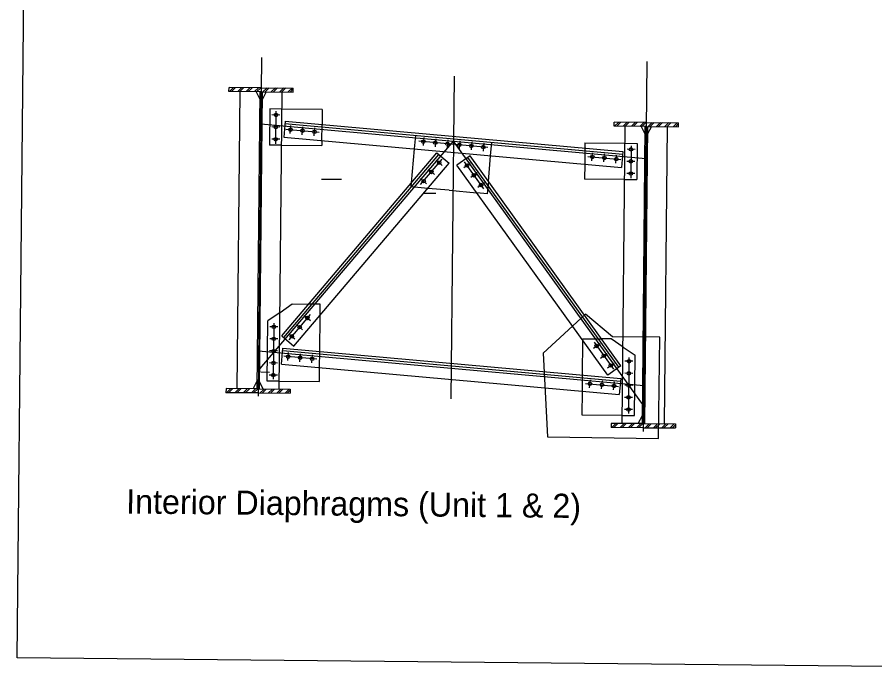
# Model space of a CAD drawing. Extents: x 632066 to 633140, y 373235 to 381884.
# Drawn here: x 632199.99 to 632217.79, y 378376.15 to 378389.8 of the extents above; entities that cross this region are included whole.
import ezdxf

# ---------------------------------------------------------------- set-up
doc = ezdxf.new("R2010")
doc.units = 0
for name, color, linetype in [('BD-EXIST-COSS', 7, 'Continuous'), ('BD-EXIST-OSB', 7, 'Continuous'), ('BD-LEGEND', 7, 'Continuous'), ('BD-PROP-COSS', 7, 'Continuous'), ('BD-PROP-OSB', 7, 'Continuous')]:
    doc.layers.add(name, color=color, linetype=linetype)

msp = doc.modelspace()

# ---------------------------------------------------------------- linework, layer by layer
at = {"layer": 'BD-EXIST-OSB'}
for p, q in [((632204.388, 378388.258), (632204.389, 378388.341)), ((632205.055, 378388.251), (632204.388, 378388.258)), ((632205.055, 378388.335), (632204.389, 378388.341)), ((632204.556, 378382.089), (632204.617, 378388.256)), ((632204.95, 378388.252), (632205.032, 378388.085)), ((632204.972, 378382.085), (632205.034, 378388.252)), ((632205.075, 378388.251), (632205.014, 378382.085)), ((632205.055, 378388.335), (632205.722, 378388.328)), ((632205.055, 378388.251), (632205.721, 378388.245)), ((632205.159, 378388.25), (632205.074, 378388.085)), ((632205.431, 378382.081), (632205.492, 378388.247)), ((632205.721, 378388.245), (632205.722, 378388.328)), ((632205.239, 378387.895), (632205.231, 378387.145)), ((632205.489, 378387.893), (632205.239, 378387.895)), ((632206.322, 378387.885), (632205.489, 378387.893)), ((632206.322, 378387.885), (632206.319, 378387.574)), ((632205.554, 378387.643), (632205.524, 378387.311)), ((632205.55, 378387.591), (632212.559, 378386.957)), ((632205.554, 378387.643), (632212.563, 378387.009)), ((632206.315, 378387.239), (632206.319, 378387.574)), ((632212.381, 378387.539), (632212.382, 378387.622)), ((632213.048, 378387.532), (632212.381, 378387.539)), ((632213.049, 378387.615), (632212.382, 378387.622)), ((632212.549, 378381.37), (632212.61, 378387.536)), ((632212.944, 378387.533), (632213.025, 378387.365)), ((632212.966, 378381.366), (632213.027, 378387.532)), ((632213.069, 378387.532), (632213.007, 378381.365)), ((632213.048, 378387.532), (632213.714, 378387.525)), ((632213.049, 378387.615), (632213.715, 378387.609)), ((632213.152, 378387.531), (632213.067, 378387.365)), ((632213.424, 378381.361), (632213.485, 378387.528)), ((632213.714, 378387.525), (632213.715, 378387.609)), ((632208.24, 378387.065), (632208.266, 378387.345)), ((632205.481, 378387.143), (632205.231, 378387.145)), ((632205.524, 378387.311), (632212.533, 378386.677)), ((632206.315, 378387.239), (632206.314, 378387.135)), ((632209.817, 378386.923), (632209.843, 378387.203)), ((632211.774, 378387.19), (632211.772, 378387.081)), ((632211.774, 378387.19), (632212.607, 378387.182)), ((632212.607, 378387.182), (632212.857, 378387.18)), ((632212.857, 378387.18), (632212.849, 378386.43)), ((632205.481, 378387.143), (632206.314, 378387.135)), ((632205.483, 378383.19), (632208.704, 378386.981)), ((632208.177, 378386.361), (632208.24, 378387.065)), ((632208.704, 378386.981), (632208.958, 378386.766)), ((632211.772, 378387.081), (632211.769, 378386.746)), ((632212.563, 378387.009), (632212.533, 378386.677)), ((632205.523, 378383.156), (632208.744, 378386.948)), ((632209.39, 378386.919), (632209.119, 378386.725)), ((632212.477, 378382.537), (632209.347, 378386.889)), ((632212.519, 378382.567), (632209.39, 378386.919)), ((632209.77, 378386.391), (632209.817, 378386.923)), ((632205.737, 378382.974), (632208.958, 378386.766)), ((632212.249, 378382.373), (632209.119, 378386.725)), ((632211.769, 378386.746), (632211.766, 378386.44)), ((632212.599, 378386.432), (632211.766, 378386.44)), ((632212.599, 378386.432), (632212.849, 378386.43)), ((632208.169, 378386.277), (632208.177, 378386.361)), ((632208.516, 378386.245), (632208.169, 378386.277)), ((632209.77, 378386.391), (632209.747, 378386.135)), ((632208.958, 378386.206), (632208.516, 378386.245)), ((632208.958, 378386.206), (632209.529, 378386.154)), ((632209.747, 378386.135), (632209.529, 378386.154)), ((632205.447, 378383.674), (632205.698, 378383.849)), ((632205.698, 378383.849), (632206.04, 378383.846)), ((632206.282, 378383.843), (632206.04, 378383.846)), ((632206.279, 378383.612), (632206.282, 378383.843)), ((632205.447, 378383.674), (632205.195, 378383.5)), ((632206.272, 378382.864), (632206.279, 378383.612)), ((632205.182, 378382.25), (632205.195, 378383.5)), ((632205.483, 378383.19), (632205.737, 378382.974)), ((632211.726, 378382.373), (632211.733, 378383.09)), ((632211.733, 378383.128), (632212.119, 378383.124)), ((632211.733, 378383.09), (632211.733, 378383.128)), ((632212.316, 378383.122), (632212.119, 378383.124)), ((632212.565, 378382.953), (632212.316, 378383.122)), ((632205.478, 378382.601), (632205.507, 378382.933)), ((632205.503, 378382.881), (632212.512, 378382.25)), ((632205.507, 378382.933), (632212.517, 378382.302)), ((632212.565, 378382.953), (632212.813, 378382.784)), ((632206.269, 378382.53), (632206.272, 378382.864)), ((632212.801, 378381.534), (632212.813, 378382.784)), ((632205.478, 378382.601), (632212.487, 378381.97)), ((632206.266, 378382.239), (632206.269, 378382.53)), ((632212.519, 378382.567), (632212.249, 378382.373)), ((632211.722, 378382.039), (632211.726, 378382.373)), ((632204.889, 378382.086), (632204.974, 378382.252)), ((632205.097, 378382.084), (632205.016, 378382.252)), ((632205.432, 378382.247), (632205.182, 378382.25)), ((632205.432, 378382.247), (632206.266, 378382.239)), ((632212.517, 378382.302), (632212.487, 378381.97)), ((632204.327, 378382.092), (632204.326, 378382.008)), ((632204.992, 378382.002), (632204.326, 378382.008)), ((632204.993, 378382.085), (632204.327, 378382.092)), ((632204.992, 378382.002), (632205.659, 378381.995)), ((632204.993, 378382.085), (632205.66, 378382.078)), ((632205.66, 378382.078), (632205.659, 378381.995)), ((632211.717, 378381.545), (632211.722, 378382.039)), ((632212.551, 378381.537), (632211.717, 378381.545)), ((632212.551, 378381.537), (632212.801, 378381.534)), ((632212.882, 378381.367), (632212.967, 378381.532)), ((632212.32, 378381.372), (632212.319, 378381.289)), ((632212.986, 378381.282), (632212.319, 378381.289)), ((632212.986, 378381.366), (632212.32, 378381.372)), ((632212.986, 378381.366), (632213.653, 378381.359)), ((632212.986, 378381.282), (632213.652, 378381.276)), ((632213.653, 378381.359), (632213.652, 378381.276))]:
    msp.add_line(p, q, dxfattribs=at)
for centre in [(632205.362, 378387.769), (632205.36, 378387.519), (632205.664, 378387.465), (632205.913, 378387.443), (632206.162, 378387.42), (632205.357, 378387.265), (632208.421, 378387.216), (632208.67, 378387.193), (632208.919, 378387.171), (632209.168, 378387.149), (632209.417, 378387.126), (632209.666, 378387.104), (632212.731, 378387.056), (632208.75, 378386.778), (632211.926, 378386.899), (632212.175, 378386.877), (632212.424, 378386.854), (632212.728, 378386.806), (632208.588, 378386.588), (632209.327, 378386.721), (632208.427, 378386.397), (632209.473, 378386.518), (632212.726, 378386.556), (632209.619, 378386.315), (632206.015, 378383.558), (632205.319, 378383.374), (632205.853, 378383.368), (632205.316, 378383.124), (632205.691, 378383.177), (632205.314, 378382.87), (632212.019, 378382.977), (632205.617, 378382.756), (632205.866, 378382.734), (632206.115, 378382.711), (632212.165, 378382.774), (632212.687, 378382.66), (632205.311, 378382.624), (632212.311, 378382.572), (632205.309, 378382.374), (632212.684, 378382.41), (632211.879, 378382.192), (632212.128, 378382.17), (632212.377, 378382.147), (632212.682, 378382.157), (632212.679, 378381.91), (632212.677, 378381.66)]:
    msp.add_circle(centre, 0.0365, dxfattribs=at)
at = {"layer": 'BD-LEGEND'}
for p, q in [((632204.398, 378388.258), (632204.482, 378388.34)), ((632204.442, 378388.258), (632204.526, 378388.34)), ((632204.572, 378388.256), (632204.656, 378388.339)), ((632204.615, 378388.256), (632204.699, 378388.338)), ((632204.745, 378388.254), (632204.83, 378388.337)), ((632204.789, 378388.254), (632204.845, 378388.309)), ((632204.845, 378388.309), (632204.873, 378388.337)), ((632204.919, 378388.253), (632205.003, 378388.335)), ((632204.962, 378388.252), (632205.047, 378388.335)), ((632205.093, 378388.251), (632205.177, 378388.334)), ((632205.136, 378388.251), (632205.22, 378388.333)), ((632205.266, 378388.249), (632205.35, 378388.332)), ((632205.31, 378388.249), (632205.394, 378388.331)), ((632205.44, 378388.248), (632205.524, 378388.33)), ((632205.483, 378388.247), (632205.567, 378388.33)), ((632205.613, 378388.246), (632205.698, 378388.328)), ((632205.657, 378388.245), (632205.722, 378388.309)), ((632212.391, 378387.538), (632212.476, 378387.621)), ((632212.435, 378387.538), (632212.519, 378387.621)), ((632212.565, 378387.537), (632212.649, 378387.619)), ((632212.608, 378387.536), (632212.693, 378387.619)), ((632212.739, 378387.535), (632212.823, 378387.617)), ((632212.782, 378387.535), (632212.838, 378387.59)), ((632212.838, 378387.59), (632212.866, 378387.617)), ((632212.912, 378387.533), (632212.996, 378387.616)), ((632212.956, 378387.533), (632213.04, 378387.615)), ((632213.086, 378387.532), (632213.17, 378387.614)), ((632213.129, 378387.531), (632213.213, 378387.614)), ((632213.259, 378387.53), (632213.344, 378387.612)), ((632213.303, 378387.529), (632213.387, 378387.612)), ((632213.433, 378387.528), (632213.517, 378387.611)), ((632213.477, 378387.528), (632213.561, 378387.61)), ((632213.607, 378387.526), (632213.691, 378387.609)), ((632213.65, 378387.526), (632213.715, 378387.59)), ((632204.336, 378382.008), (632204.42, 378382.091)), ((632204.379, 378382.008), (632204.464, 378382.09)), ((632204.51, 378382.007), (632204.594, 378382.089)), ((632204.553, 378382.006), (632204.637, 378382.089)), ((632204.683, 378382.005), (632204.767, 378382.087)), ((632204.727, 378382.004), (632204.783, 378382.059)), ((632204.783, 378382.059), (632204.811, 378382.087)), ((632204.857, 378382.003), (632204.941, 378382.086)), ((632204.9, 378382.003), (632204.984, 378382.085)), ((632205.031, 378382.001), (632205.115, 378382.084)), ((632205.074, 378382.001), (632205.158, 378382.083)), ((632205.204, 378382), (632205.288, 378382.082)), ((632205.248, 378381.999), (632205.332, 378382.082)), ((632205.378, 378381.998), (632205.462, 378382.08)), ((632205.421, 378381.997), (632205.505, 378382.08)), ((632205.551, 378381.996), (632205.635, 378382.079)), ((632205.595, 378381.996), (632205.66, 378382.059)), ((632212.329, 378381.289), (632212.413, 378381.371)), ((632212.373, 378381.288), (632212.457, 378381.371)), ((632212.503, 378381.287), (632212.587, 378381.37)), ((632212.546, 378381.287), (632212.631, 378381.369)), ((632212.677, 378381.285), (632212.761, 378381.368)), ((632212.72, 378381.285), (632212.776, 378381.34)), ((632212.776, 378381.34), (632212.804, 378381.367)), ((632212.85, 378381.284), (632212.934, 378381.366)), ((632212.894, 378381.283), (632212.978, 378381.366)), ((632213.024, 378381.282), (632213.108, 378381.364)), ((632213.067, 378381.281), (632213.151, 378381.364)), ((632213.197, 378381.28), (632213.282, 378381.363)), ((632213.241, 378381.28), (632213.325, 378381.362)), ((632213.371, 378381.278), (632213.455, 378381.361)), ((632213.414, 378381.278), (632213.499, 378381.36)), ((632213.545, 378381.277), (632213.629, 378381.359)), ((632213.588, 378381.276), (632213.653, 378381.34))]:
    msp.add_line(p, q, dxfattribs=at)
at = {"layer": 'BD-PROP-COSS'}
for p, q in [((632206.307, 378386.44), (632206.722, 378386.436)), ((632206.307, 378386.44), (632206.722, 378386.436)), ((632208.68, 378386.137), (632208.421, 378386.14)), ((632211.785, 378383.634), (632210.909, 378382.828)), ((632212.346, 378383.168), (632211.785, 378383.634)), ((632213.329, 378383.163), (632212.346, 378383.168)), ((632213.303, 378381.057), (632213.329, 378383.163)), ((632210.909, 378382.828), (632210.998, 378381.091)), ((632205.226, 378382.43), (632205.05, 378382.431)), ((632210.998, 378381.091), (632213.303, 378381.057))]:
    msp.add_line(p, q, dxfattribs=at)
msp.add_lwpolyline([(632200.26, 378403.442), (632235.587, 378403.091), (632235.319, 378376.155), (632199.993, 378376.506)], close=True, dxfattribs=at)
at = {"layer": 'BD-PROP-OSB'}
for p, q in [((632205.062, 378388.961), (632204.992, 378381.938)), ((632213.061, 378388.881), (632212.985, 378381.206)), ((632209.058, 378388.573), (632208.991, 378381.878)), ((632205.446, 378387.768), (632205.279, 378387.77)), ((632205.363, 378387.845), (632205.356, 378387.171)), ((632205.048, 378387.585), (632213.041, 378386.865)), ((632205.443, 378387.518), (632205.276, 378387.52)), ((632205.656, 378387.382), (632205.671, 378387.548)), ((632205.905, 378387.36), (632205.92, 378387.526)), ((632206.154, 378387.337), (632206.169, 378387.503)), ((632205.57, 378387.474), (632206.256, 378387.412)), ((632204.997, 378382.46), (632209.045, 378387.225)), ((632205.441, 378387.268), (632205.274, 378387.27)), ((632209.761, 378387.095), (632208.327, 378387.224)), ((632208.429, 378387.299), (632208.414, 378387.133)), ((632208.678, 378387.276), (632208.663, 378387.11)), ((632208.927, 378387.254), (632208.912, 378387.088)), ((632212.99, 378381.741), (632209.045, 378387.225)), ((632209.176, 378387.232), (632209.161, 378387.066)), ((632209.425, 378387.209), (632209.41, 378387.043)), ((632209.674, 378387.187), (632209.659, 378387.021)), ((632211.918, 378386.816), (632211.933, 378386.982)), ((632212.814, 378387.055), (632212.647, 378387.057)), ((632212.731, 378387.132), (632212.725, 378386.458)), ((632208.365, 378386.325), (632208.812, 378386.85)), ((632208.814, 378386.724), (632208.687, 378386.832)), ((632209.674, 378386.238), (632209.272, 378386.797)), ((632211.832, 378386.908), (632212.518, 378386.846)), ((632212.167, 378386.794), (632212.182, 378386.96)), ((632212.416, 378386.771), (632212.431, 378386.937)), ((632212.811, 378386.805), (632212.645, 378386.807)), ((632208.652, 378386.534), (632208.525, 378386.642)), ((632209.395, 378386.769), (632209.26, 378386.672)), ((632208.49, 378386.343), (632208.363, 378386.451)), ((632209.541, 378386.566), (632209.406, 378386.469)), ((632212.809, 378386.555), (632212.642, 378386.557)), ((632209.687, 378386.363), (632209.551, 378386.266)), ((632206.076, 378383.63), (632205.63, 378383.105)), ((632205.952, 378383.612), (632206.079, 378383.504)), ((632205.319, 378383.45), (632205.308, 378382.29)), ((632205.79, 378383.422), (632205.917, 378383.314)), ((632205.402, 378383.373), (632205.235, 378383.374)), ((632205.628, 378383.231), (632205.755, 378383.123)), ((632205.399, 378383.123), (632205.233, 378383.124)), ((632211.964, 378383.054), (632212.366, 378382.495)), ((632204.999, 378382.877), (632212.994, 378382.157)), ((632205.397, 378382.873), (632205.23, 378382.874)), ((632211.951, 378382.929), (632212.087, 378383.026)), ((632206.209, 378382.703), (632205.527, 378382.764)), ((632205.61, 378382.673), (632205.624, 378382.839)), ((632205.859, 378382.651), (632205.873, 378382.817)), ((632206.108, 378382.628), (632206.122, 378382.794)), ((632212.097, 378382.726), (632212.233, 378382.823)), ((632212.688, 378382.736), (632212.676, 378381.577)), ((632205.394, 378382.623), (632205.228, 378382.624)), ((632212.243, 378382.523), (632212.379, 378382.62)), ((632212.77, 378382.659), (632212.604, 378382.661)), ((632205.392, 378382.373), (632205.225, 378382.374)), ((632212.768, 378382.409), (632212.601, 378382.411)), ((632211.785, 378382.201), (632212.471, 378382.139)), ((632211.872, 378382.109), (632211.887, 378382.275)), ((632212.121, 378382.087), (632212.136, 378382.253)), ((632212.37, 378382.064), (632212.385, 378382.23)), ((632212.765, 378382.159), (632212.599, 378382.161)), ((632212.763, 378381.909), (632212.596, 378381.911)), ((632212.76, 378381.659), (632212.594, 378381.661))]:
    msp.add_line(p, q, dxfattribs=at)

# ---------------------------------------------------------------- texts
at = {"layer": 'BD-EXIST-COSS'}
msp.add_text('Interior Diaphragms (Unit 1 & 2)', height=0.5, rotation=359.4304, dxfattribs=at).set_placement((632202.253, 378379.502))

doc.saveas('drawing.dxf')
